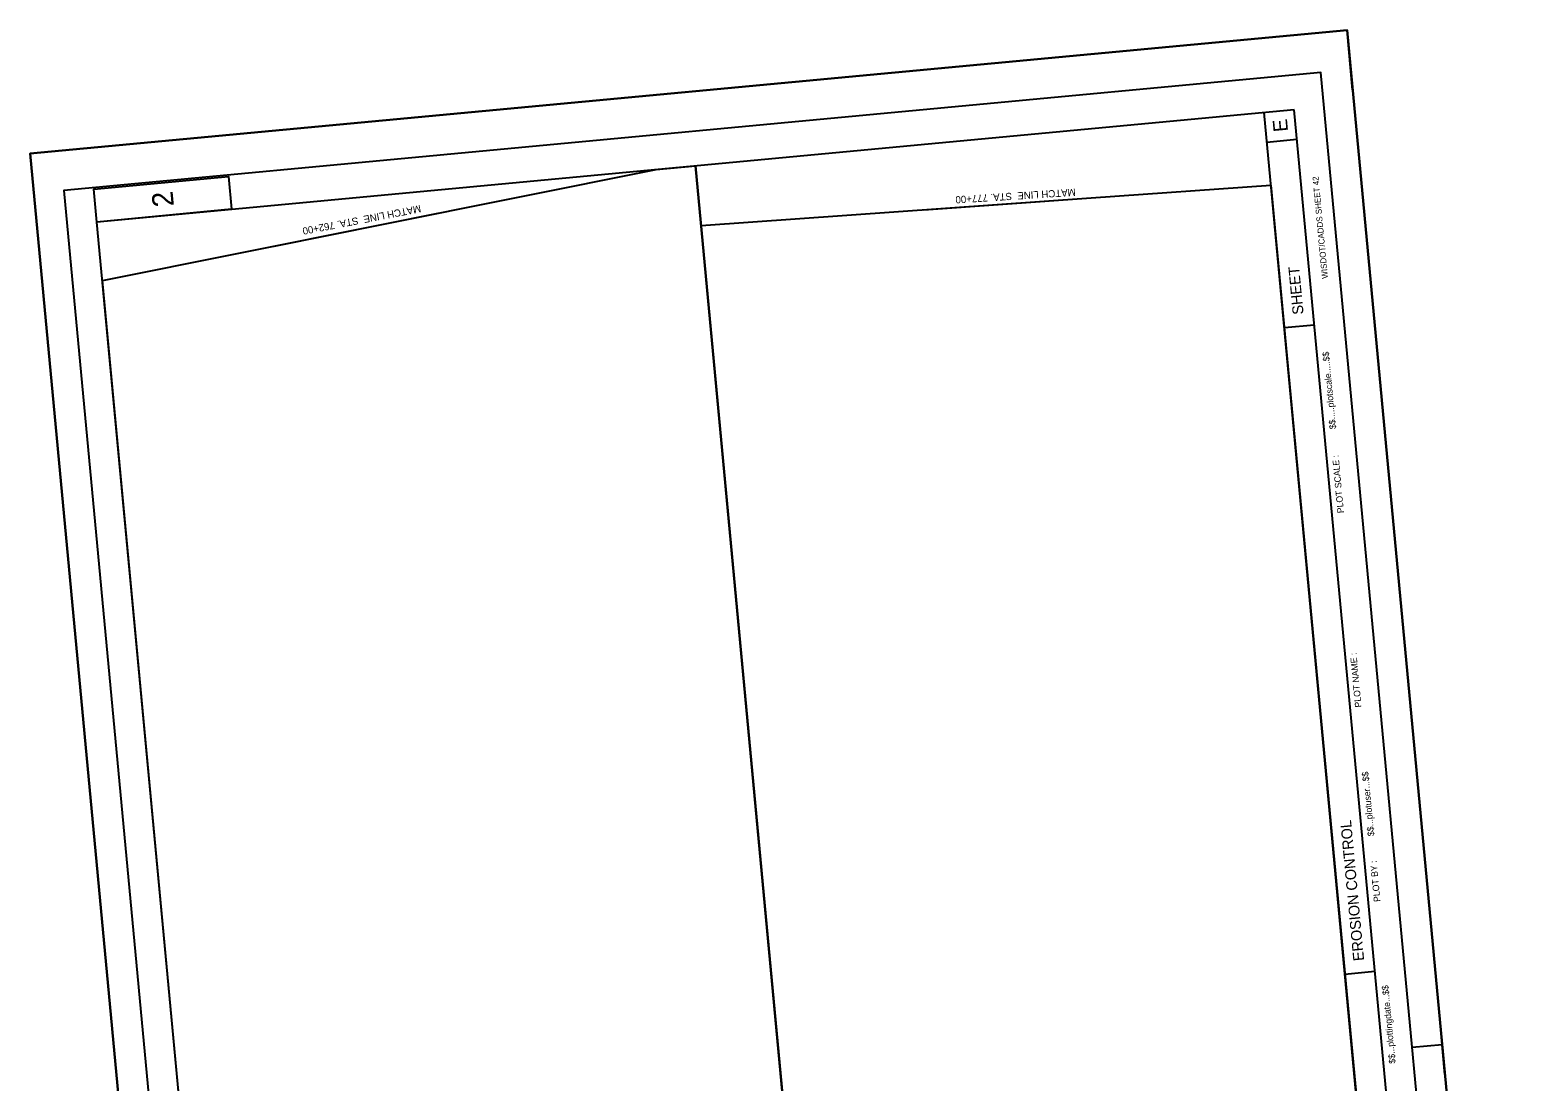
# Model space of a CAD drawing. Extents: x 356181 to 357435, y 196482 to 198277.
# Drawn here: x 356181 to 357435, y 197402 to 198277 of the extents above; entities that cross this region are included whole.
import ezdxf

# ---------------------------------------------------------------- set-up
doc = ezdxf.new("R2010")
doc.units = 0
for name, color, linetype in [('Default', 7, 'Continuous'), ('P_SHTIDX_4 [KAPUR_CADDS_LEVELS]', 7, 'Continuous'), ('P_TXT_Plan 1 [KAPUR_CADDS_LEVELS]', 7, 'Continuous'), ('P_TXT_Plan 3 [KAPUR_CADDS_LEVELS]', 7, 'Continuous'), ('P_TXT_Plan 4 [KAPUR_CADDS_LEVELS]', 7, 'Continuous'), ('P_TXT_Plan 4_TEXT [KAPUR_CADDS_LEVELS]', 7, 'Continuous'), ('PLT_Sheet_Info', 7, 'Continuous')]:
    doc.layers.add(name, color=color, linetype=linetype)

msp = doc.modelspace()

# ---------------------------------------------------------------- linework, layer by layer
at = {"layer": 'Default'}
for points in [[(356241.5, 198068.7), (356702.1, 198161.1), (356734.8, 198164.1), (356881.8, 196596), (356881.7, 196597.3), (356375.2, 196643.3)], [(356241.5, 198068.7), (356702.1, 198161.1), (356734.8, 198164.1), (356881.8, 196596), (356881.7, 196597.3), (356375.2, 196643.3)], [(356241.5, 198068.7), (356702.1, 198161.1), (356734.8, 198164.1), (356881.8, 196596), (356881.7, 196597.3), (356375.2, 196643.3)], [(356241.5, 198068.7), (356702.1, 198161.1), (356734.8, 198164.1), (356881.8, 196596), (356881.7, 196597.3), (356375.2, 196643.3)], [(356241.5, 198068.7), (356702.1, 198161.1), (356734.8, 198164.1), (356881.8, 196596), (356881.7, 196597.3), (356375.2, 196643.3)], [(356241.5, 198068.7), (356702.1, 198161.1), (356734.8, 198164.1), (356881.8, 196596), (356881.7, 196597.3), (356375.2, 196643.3)], [(356739.4, 198114.4), (357063.7, 198137.5), (357213.3, 198148.1), (357353.4, 196654.3), (357353.4, 196654.3), (356879.5, 196620.6)], [(356739.4, 198114.4), (357063.7, 198137.5), (357213.3, 198148.1), (357353.4, 196654.3), (357353.4, 196654.3), (356879.5, 196620.6)], [(356739.4, 198114.4), (357063.7, 198137.5), (357213.3, 198148.1), (357353.4, 196654.3), (357353.4, 196654.3), (356879.5, 196620.6)], [(356739.4, 198114.4), (357063.7, 198137.5), (357213.3, 198148.1), (357353.4, 196654.3), (357353.4, 196654.3), (356879.5, 196620.6)], [(356739.4, 198114.4), (357063.7, 198137.5), (357213.3, 198148.1), (357353.4, 196654.3), (357353.4, 196654.3), (356879.5, 196620.6)], [(356739.4, 198114.4), (357063.7, 198137.5), (357213.3, 198148.1), (357353.4, 196654.3), (357353.4, 196654.3), (356879.5, 196620.6)]]:
    msp.add_lwpolyline(points, close=True, dxfattribs=at)
at = {"layer": 'P_SHTIDX_4 [KAPUR_CADDS_LEVELS]'}
for p, q in [((357276.6, 198277), (357226.8, 198272.3)), ((357281.3, 198227.2), (357276.6, 198277)), ((357232.6, 198210.8), (356236.9, 198117.4)), ((357379.6, 196642.7), (357232.6, 198210.8)), ((357354.7, 196640.4), (357207.7, 198208.5)), ((357234.9, 198185.9), (357210, 198183.6)), ((356231.2, 198178.9), (356181.4, 198174.3)), ((356186.1, 198124.5), (356181.4, 198174.3)), ((356736.3, 198148), (356734.8, 198164.1)), ((356384, 196549.3), (356236.9, 198117.4)), ((357249.4, 198031.6), (357224.5, 198029.3)), ((356881.8, 196596), (356763.6, 197856.3)), ((357299.8, 197494), (357274.9, 197491.6)), ((357358.1, 197408.3), (357353.4, 197458.1)), ((357355.7, 197433.2), (357330.8, 197430.8))]:
    msp.add_line(p, q, dxfattribs=at)
msp.add_lwpolyline([(356236.9, 198117.4), (356234.4, 198144.8), (356346.4, 198155.3), (356348.9, 198128)], close=True, dxfattribs=at)
at = {"layer": 'P_TXT_Plan 1 [KAPUR_CADDS_LEVELS]'}
msp.add_line((356881.8, 196596), (356734.8, 198164.1), dxfattribs=at)
at = {"layer": 'P_TXT_Plan 4 [KAPUR_CADDS_LEVELS]'}
for p, q in [((356924.7, 198127.6), (357063.7, 198137.5)), ((356384.2, 198097.3), (356520.8, 198124.7))]:
    msp.add_line(p, q, dxfattribs=at)
at = {"layer": 'P_TXT_Plan 4_TEXT [KAPUR_CADDS_LEVELS]'}
msp.add_lwpolyline([(356340.1, 196481.7), (356181.4, 198174.3), (357276.6, 198277), (357435.3, 196584.4)], close=True, dxfattribs=at)
at = {"layer": 'PLT_Sheet_Info'}
for points in [[(357435.3, 196584.4), (357276.6, 198277), (356181.4, 198174.3), (356340.1, 196481.7)], [(357409.3, 196594), (357254.8, 198241.8), (356209.4, 198143.7), (356363.9, 196496)]]:
    msp.add_lwpolyline(points, close=True, dxfattribs=at)

# ---------------------------------------------------------------- texts
at = {"layer": 'P_SHTIDX_4 [KAPUR_CADDS_LEVELS]'}
for s, height, rotation, p in [('E', 12, 95.3579, (357227.6, 198192.9)), ('WISDOT/CADDS SHEET 42', 5, 95.3579, (357260.8, 198070.5)), ('2', 17.5, 95.3579, (356301, 198130.7)), ('SHEET ', 9, 95.3579, (357240.5, 198040.8)), ('$$.....plotscale.....$$', 5.4, 95.3579, (357267.5, 197945.4)), ('PLOT SCALE : ', 5.4, 95.3579, (357274.1, 197875.5)), ('PLOT NAME :                      ', 5.4, 95.3579, (357288.7, 197713.9)), ('$$...plotuser...$$', 5.4, 95.3578, (357299.3, 197606.9)), ('EROSION CONTROL', 9, 95.3579, (357290.9, 197503.2)), ('PLOT BY :', 5.4, 95.3578, (357304.4, 197552.2)), ('$$...plottingdate...$$', 5.4, 95.3578, (357317, 197417.7))]:
    msp.add_text(s, height=height, rotation=rotation, dxfattribs=at).set_placement(p)
at = {"layer": 'P_TXT_Plan 3 [KAPUR_CADDS_LEVELS]'}
for s, rotation, p in [('MATCH LINE  STA. 777+00', 183.6562, (357050.7, 198145.2)), ('MATCH LINE  STA. 762+00', 190.9331, (356505.8, 198131.6))]:
    msp.add_text(s, height=6, rotation=rotation, dxfattribs=at).set_placement(p)

doc.saveas('drawing.dxf')
